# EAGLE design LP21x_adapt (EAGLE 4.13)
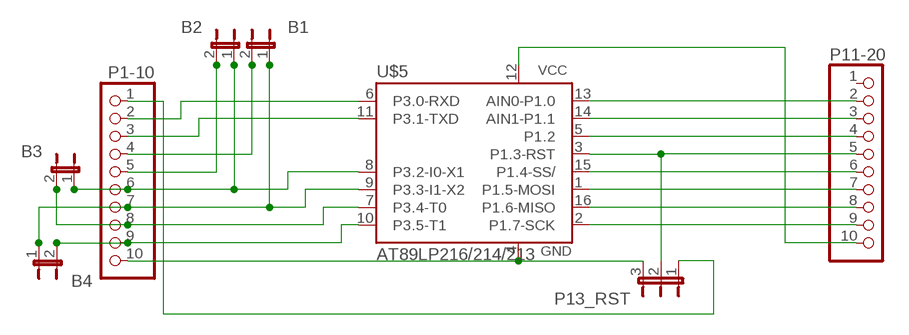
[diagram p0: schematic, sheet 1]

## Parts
B1  JP1EPP1S  [JP1S]
B2  JP1EPP1S  [JP1S]
B3  JP1EPP1S  [JP1S]
B4  JP1EPP1S  [JP1S]
P1-10  PINHD-1X10RND  [1X10RND]
P11-20  PINHD-1X10RND  [1X10RND]
P13_RST  JP2EJP2S  [JP2S]
U$5  AT89LP216/214/213  AT89LP216  [TSSOP16]

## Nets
N$43: P1-10.1 P13_RST.1
N$44: P11-20.5 P13_RST.2 U$5.3(P1.3-RST)
N$46: P1-10.2 U$5.6(P3.0-RXD)
N$47: P1-10.3 U$5.11(P3.1-TXD)
N$50: B2.2 P1-10.5
N$51: B1.2 P1-10.4
N$52: B2.1 B3.1 P1-10.6 U$5.8(P3.2-I0-X1)
N$53: B1.1 B4.1 P1-10.7 U$5.9(P3.3-I1-X2)
N$55: B3.2 P1-10.8 U$5.7(P3.4-T0)
N$56: B4.2 P1-10.9 U$5.10(P3.5-T1)
N$57: P11-20.2 U$5.13(AIN0-P1.0)
N$58: P11-20.3 U$5.14(AIN1-P1.1)
N$59: P11-20.4 U$5.5(P1.2)
N$60: P11-20.6 U$5.15(P1.4-SS/)
N$61: P11-20.7 U$5.1(P1.5-MOSI)
N$62: P11-20.8 U$5.16(P1.6-MISO)
N$63: P11-20.9 U$5.2(P1.7-SCK)
P10GND: P1-10.10 P13_RST.3 U$5.4(GND)
P20VCC: P11-20.10 U$5.12(VCC)
Unconnected: P11-20.1

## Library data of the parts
B1-B4 = jumper:JP1E: JUMPER
P1-10 P11-20 = pinhead:PINHD-1X10: PIN HEADER
P13_RST = jumper:JP2E: JUMPER
U$5 = atmel:AT89LP216

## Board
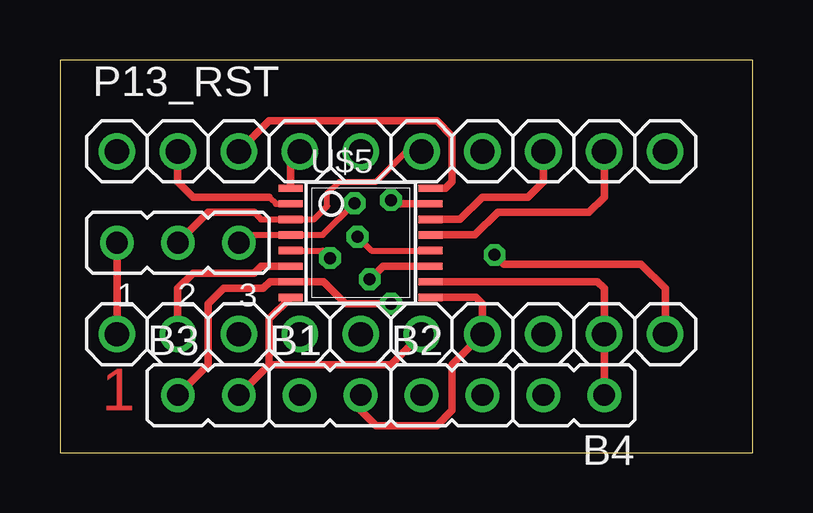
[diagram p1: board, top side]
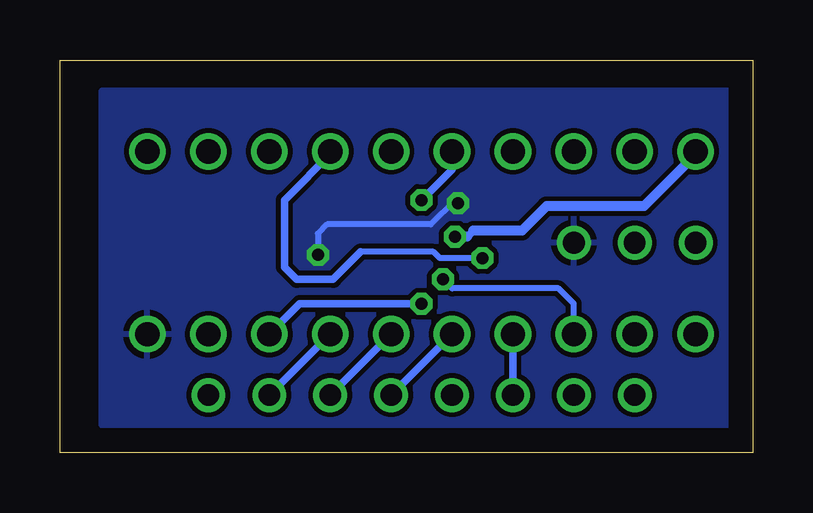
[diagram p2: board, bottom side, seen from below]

Size 28.88 x 16.37 mm. Coordinates in mm from the lower left corner, seen from the top.
Outline: 0,0 28.88,0 28.88,16.37 0,16.37 0,0
Copper layers (1*16): Top 0.035mm / dielectric 1.5mm / Bottom 0.035mm
Design rules "default": minimum track width 10mil, minimum drill 18mil, track to track 8mil, track to pad 8mil, pad to pad 8mil, via to via 8mil, smd to smd 8mil, copper to edge 40mil, drill to drill 8mil, minimum pad ring 10mil, minimum via ring 8mil, stop-mask expansion 4mil, vias tented up to drill 0mil, thermal gap 10mil

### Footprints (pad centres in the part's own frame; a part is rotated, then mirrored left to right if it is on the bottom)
JP1S = drill 0.9 round: 1 0,1.27; 2 0,-1.27
1X10RND = drill 1.016 round: 1 -11.43,0; 2 -8.89,0; 3 -6.35,0; 4 -3.81,0; 5 -1.27,0; 6 1.27,0; 7 3.81,0; 8 6.35,0; 9 8.89,0; 10 11.43,0
JP2S = drill 0.9 round: 1 -2.54,0; 2 0,0; 3 2.54,0
TSSOP16 = smd 0.305 x 0.991: 1 -2.275,-2.918; 2 -1.625,-2.918; 3 -0.975,-2.918; 4 -0.325,-2.918; 5 0.325,-2.918; 6 0.975,-2.918; 7 1.625,-2.918; 8 2.275,-2.918; 9 2.275,2.918; 10 1.625,2.918; 11 0.975,2.918; 12 0.325,2.918; 13 -0.325,2.918; 14 -0.975,2.918; 15 -1.625,2.918; 16 -2.275,2.918

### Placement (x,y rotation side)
B1  11.27,2.41 270 top
B2  16.34,2.41 270 top
B3  6.18,2.41 270 top
B4  21.42,2.41 90 top
P1-10  13.81,4.95 0 top
P11-20  13.81,12.57 180 top
P13_RST  4.92,8.76 0 top
U$5  12.54,8.76 270 top

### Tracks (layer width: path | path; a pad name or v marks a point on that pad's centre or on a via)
N$43
  Top 0.305: P1-10.1 P13_RST.1
N$44
  Top 0.254: 8.09,10.03 8.38,9.73 U$5.3 10.59,9.73 11.14,10.28 11.14,10.79 11.65,11.3 13.17,11.3 14.44,12.57 P11-20.5
  Top 0.305: 8.09,10.03 6.18,10.03 P13_RST.2
N$46
  Top 0.305: U$5.6 8.38,7.78 8.09,7.49 5.55,7.49 4.92,6.85 P1-10.2
N$47  (via drill 0.5)
  Top 0.305: U$5.11 13.46,7.78 v12.92,7.23
  Bottom 0.254: v12.92,7.23 12.54,6.85 8.09,6.85 7.46,6.22 P1-10.3
N$50
  Bottom 0.305: B2.2 P1-10.5
N$51
  Bottom 0.305: B1.2 P1-10.4
N$52
  Top 0.305: U$5.8 9.62,6.47 8.73,5.58 8.73,3.68 | B3.1 8.73,3.68 | P1-10.6 13.81,3.68 8.73,3.68
  Bottom 0.305: P1-10.6 B2.1
N$53
  Top 0.305: U$5.9 17.35,6.48 17.61,6.22 P1-10.7 16.34,3.68 16.34,1.77 15.71,1.14 13.17,1.14 12.54,1.77 B1.1
  Bottom 0.305: P1-10.7 B4.1
N$55  (via drill 0.5)
  Top 0.305: B3.2 6.18,3.68 6.18,6.22 6.82,6.85 8.47,6.85 8.75,7.13 U$5.7 10.99,7.13 11.9,6.22 v13.81,6.22
  Bottom 0.305: v13.81,6.22 18.88,6.22 P1-10.8
N$56
  Top 0.305: U$5.10 22.41,7.13 22.7,6.85 P1-10.9 B4.2
N$57
  Top 0.305: U$5.13 17.3,9.08 18.25,10.03 22.06,10.03 22.7,10.66 P11-20.2
N$58
  Top 0.305: U$5.14 16.68,9.73 17.61,10.66 19.52,10.66 20.15,11.3 P11-20.3
N$59  (via drill 0.5)
  Top 0.254: U$5.5 10.96,8.43 v11.27,8.12
  Bottom 0.254: 16.34,8.38 13.3,8.38 13.04,8.12 v11.27,8.12
  Bottom 0.305: 16.34,8.38 17.49,7.23 19.01,7.23 19.52,7.74 19.52,10.54 17.49,12.57 P11-20.4
N$60  (via drill 0.5)
  Top 0.305: U$5.15 14.16,10.38 v13.81,10.54
  Bottom 0.305: v13.81,10.54 12.54,11.81 P11-20.6
N$61
  Top 0.305: U$5.1 9.62,12.19 P11-20.7
N$62
  Top 0.305: U$5.16 16.08,11.03 16.34,11.3 16.34,13.2 15.71,13.84 8.73,13.84 P11-20.8
N$63
  Top 0.254: U$5.2 9.01,10.38 8.73,10.66
  Top 0.305: 8.73,10.66 5.55,10.66 4.92,11.3 P11-20.9
P10GND  (via drill 0.5)
  Top 0.254: P13_RST.3 7.78,9.08 U$5.4 10.96,9.08 v12.28,10.41
  Top 0.305: v18.12,8.25 18.5,7.87 24.22,7.87 25.23,6.85 P1-10.10
  Bottom 0.254: v18.12,8.25 18.12,9.14 17.74,9.52 13.42,9.52 12.41,10.54 v12.28,10.41
  pour Bottom: 0.47,15.11 0.47,1.14 27.14,1.14 27.14,15.11
P20VCC  (via drill 0.5)
  Top 0.254: U$5.12 12.99,8.43 v12.41,9.01
  Bottom 0.254: P11-20.10 2.25,12.57
  Bottom 0.305: 11.65,9.27 11.9,9.01
  Bottom 0.406: 2.25,12.57 4.53,10.28 8.6,10.28 9.61,9.27 11.65,9.27 | 11.9,9.01 v12.41,9.01

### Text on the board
Top: 1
